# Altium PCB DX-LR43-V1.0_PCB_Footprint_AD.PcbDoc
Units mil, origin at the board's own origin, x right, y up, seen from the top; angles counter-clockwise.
Board outline 1181.1 x 1181.1 mil, 2 copper layers (Top, Bottom), stack 12.7 mil thick; 1 components, 0 nets, 16 pads, 0 vias.
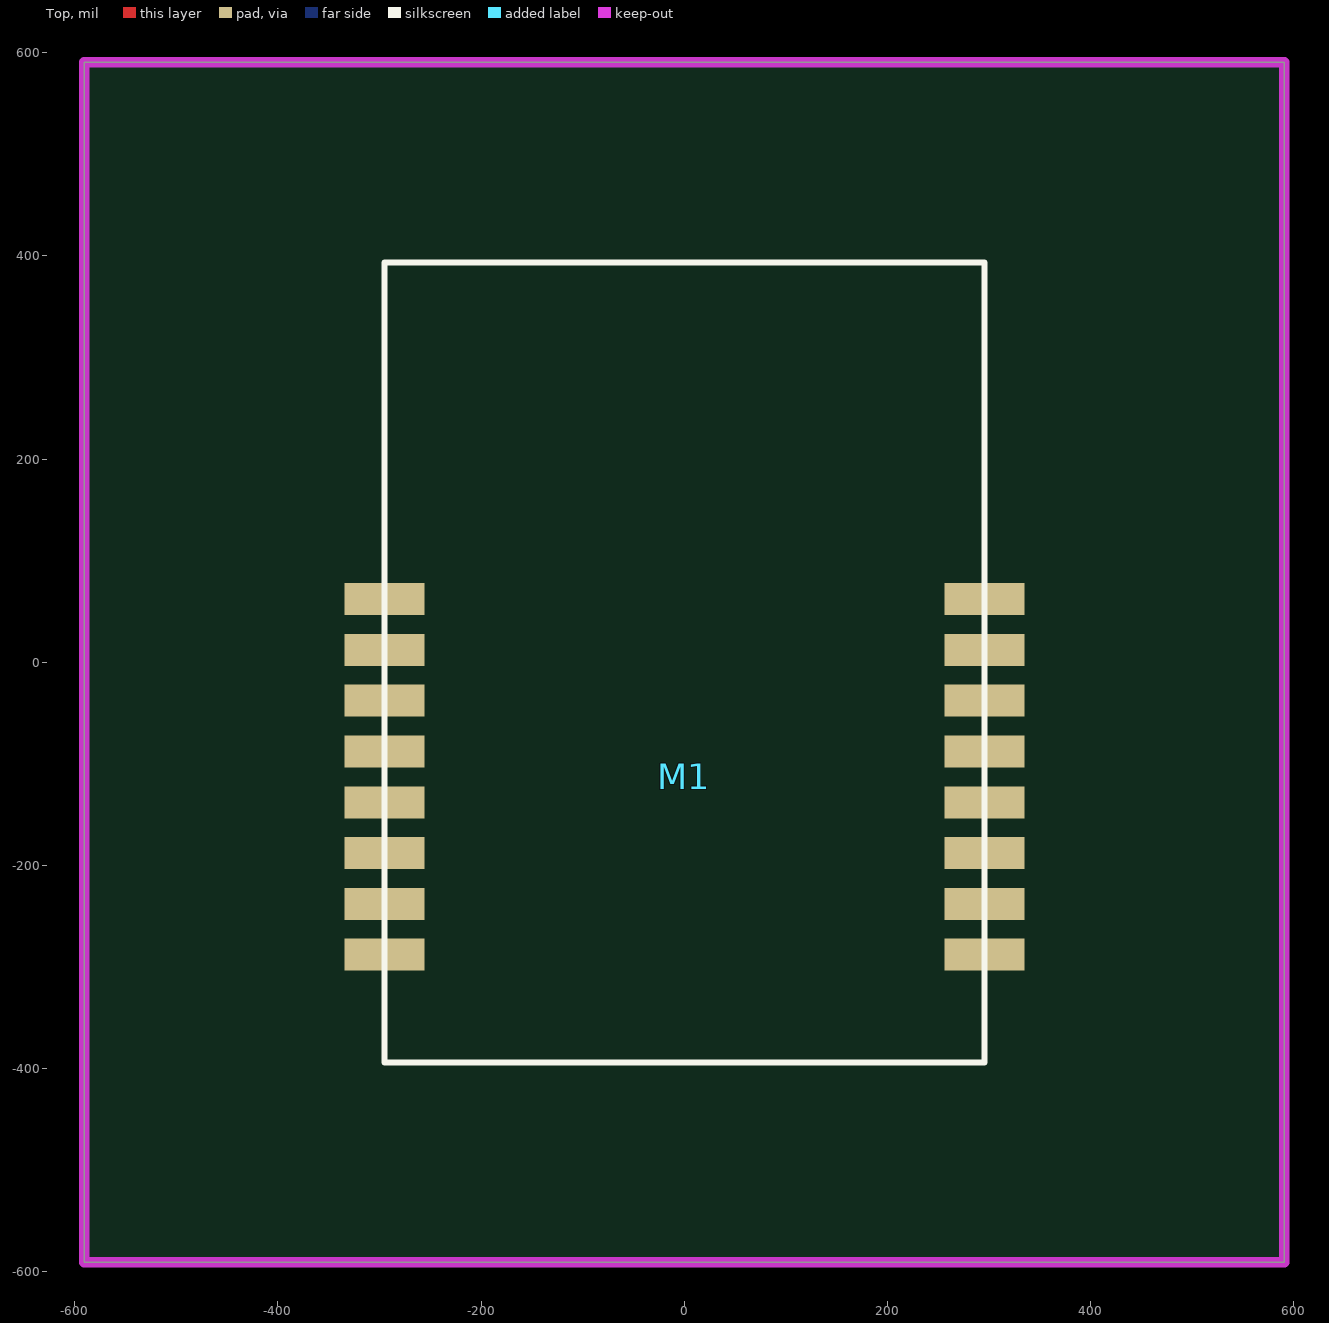
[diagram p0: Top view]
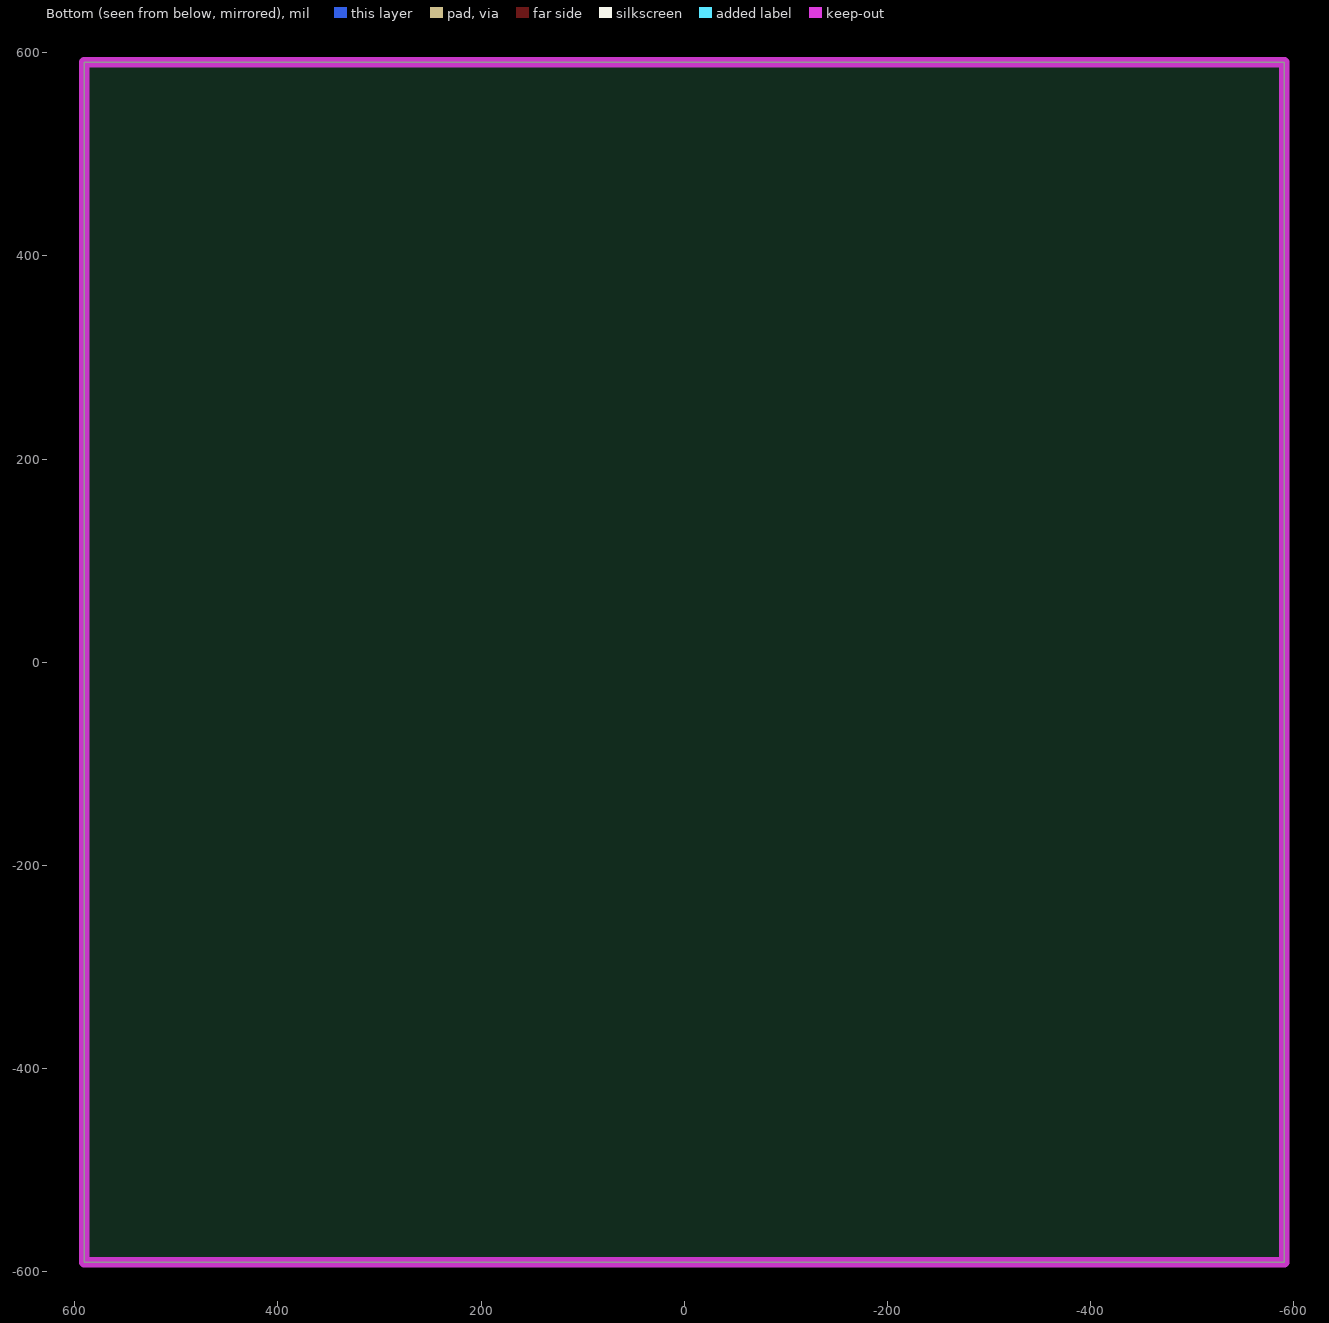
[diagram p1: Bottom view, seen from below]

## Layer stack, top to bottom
Solder Mask Top: solder mask 0.4, Solder Resist, Dk 3.5
Top: signal copper 1.35
Dielectric 1: dielectric 10, FR-4, Dk 4.3
Bottom: signal copper 1.35
Solder Mask Bottom: solder mask 0.4, Solder Resist, Dk 3.5

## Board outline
-590.55,590.55 590.55,590.55 590.55,-590.55 -590.55,-590.55

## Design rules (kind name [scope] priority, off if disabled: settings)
Clearance "Clearance - Default - DEFAULT - Via" [IsVia vs IsVia] p1: gap=6 ignorepadtopadclearanceinfootprint=FALSE
Clearance "Clearance - Default - DEFAULT- SMD" [IsVia vs IsSMTPin] p2: gap=6 ignorepadtopadclearanceinfootprint=FALSE
Clearance "Clearance - Default - DEFAULT - Net" [All] p3: gap=6 ignorepadtopadclearanceinfootprint=FALSE except(10: Arc-Hole Track-Hole SMDPad-Hole THPad-Hole Via-Hole Fill-Hole Poly-Hole Region-Hole Text-Text Text-Hole)
ComponentClearance "ComponentClearance - Default - DEFAULT" [All] p1: gap=6 collisioncheckmode=3 verticalgap=10 showdistances=FALSE
FanoutControl Fanout_SOIC [IsSOIC] p1: bgadir=Out bgaviamode=Centered fanoutstyle=Auto fanoutdirection=Alternating viagrid=1 // Fanout_SOIC (Default Rule)
FanoutControl Fanout_Small [(CompPinCount < 5)] p2: bgadir=Out bgaviamode=Centered fanoutstyle=Auto fanoutdirection=OutThenIn viagrid=1 // Fanout_Small (Default Rule)
FanoutControl Fanout_LCC [IsLCC] p3: bgadir=Out bgaviamode=Centered fanoutstyle=Auto fanoutdirection=Alternating viagrid=1 // Fanout_LCC (Default Rule)
FanoutControl Fanout_BGA [IsBGA] p4: bgadir=Out bgaviamode=Centered fanoutstyle=Auto fanoutdirection=Alternating viagrid=1 // Fanout_BGA (Default Rule)
HoleToHoleClearance "HoleToHoleClearance - Default - DEFAULT" [All] p1: gap=6 allowstackedmicrovias=TRUE
Length "Default Length" [All] p1: maxlimit=50000 minlimit=0
MaxMinImpedance "Default Impedance" [All] p1: minimum=50.00 maximum=150.0
ParallelSegment "Default Parallel Segment Same Layer" [All] p1: limit=1000 gap=200
ParallelSegment "Default Parallel Segment Adjasent" [All] p2: limit=1000 gap=200
RoutingLayers "RoutingLayers - Default - DEFAULT" [All] p1: top layer_v5=TRUE bottom layer_v5=TRUE
RoutingPriority "RoutingPriority - Default - DEFAULT" [All] p1: routingpriority=3
RoutingTopology "Default Routing Topology" [All] p1: topology=Shortest
RoutingVias "RoutingVias - Default - DEFAULT" [All] p1: holewidth=37 width=55 viastyle="Through Hole" minholewidth=37 minwidth=55 maxholewidth=37 maxwidth=55
SMDToCorner "SMDToCorner - Default - DEFAULT" [All] p1: distance=60000
SolderMaskExpansion [All] p1: expansion=4 istentingtop=FALSE
Width "Default Width" [All] p1: maxlimit=6 minlimit=6 preferedwidth=6
18 further rules are at their usual default settings.

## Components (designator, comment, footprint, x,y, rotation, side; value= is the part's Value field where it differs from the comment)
M1 "DX-LR43" DX-LR43 0,0 r0 top

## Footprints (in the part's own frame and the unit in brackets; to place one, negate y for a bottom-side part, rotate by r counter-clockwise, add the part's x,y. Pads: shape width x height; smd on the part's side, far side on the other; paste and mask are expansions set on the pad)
DX-LR43 [mm]
  rect 2x0.8 smd: 1(-7.5,1.58) 2(-7.5,0.31) 3(-7.5,-0.96) 4(-7.5,-2.23) 5(-7.5,-3.5) 6(-7.5,-4.77) 7(-7.5,-6.04) 8(-7.5,-7.31) 9(7.5,-7.31) 10(7.5,-6.04) 11(7.5,-4.77) 12(7.5,-3.5) 13(7.5,-2.23) 14(7.5,-0.96) 15(7.5,0.31) 16(7.5,1.58)
  silkscreen extent -7.5,-10 7.5,10

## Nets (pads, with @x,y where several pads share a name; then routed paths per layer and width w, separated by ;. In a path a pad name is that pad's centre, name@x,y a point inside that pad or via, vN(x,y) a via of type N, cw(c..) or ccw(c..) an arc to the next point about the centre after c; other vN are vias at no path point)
pads on no net: M1.1 M1.2 M1.3 M1.4 M1.5 M1.6 M1.7 M1.8 M1.9 M1.10 M1.11 M1.12 M1.13 M1.14 M1.15 M1.16

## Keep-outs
Keep-Out Layer:
  the board outline again, w10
